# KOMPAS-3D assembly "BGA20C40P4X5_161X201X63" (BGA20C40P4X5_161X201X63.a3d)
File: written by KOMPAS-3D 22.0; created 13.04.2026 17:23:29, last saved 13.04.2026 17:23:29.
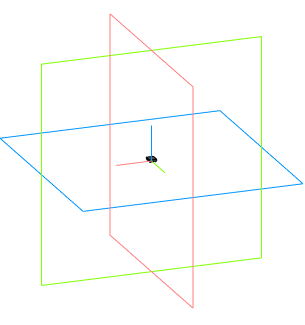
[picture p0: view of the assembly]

Document properties: Автор: Andrey; Полное имя файла: C:\Users\User1\Documents\BGA20C40P4X5_161X201X63.a3d

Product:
- Component [assembly]: ASSEMBLY  | qty 1  | source file: ASSEMBLY_3.a3d
- Part/product: BGA20C40P4X5_161X201X63
    Комментарий: BGA20C40P4X5_161X201X63

Referenced files in C:\Users\User1\Documents\: ASSEMBLY_3.a3d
